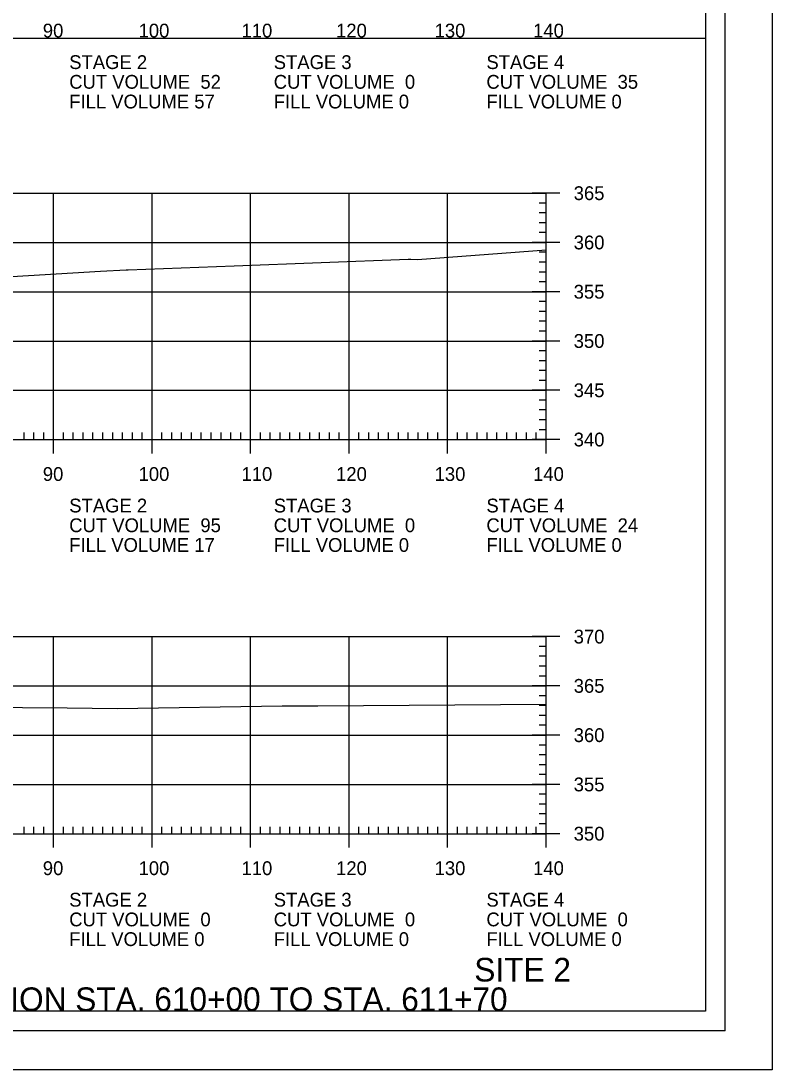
# Model space of a CAD drawing. Extents: x 1368910 to 1369601, y 380116 to 380950.
# Drawn here: x 1369524.3 to 1369600.5, y 380310.4 to 380416.9 of the extents above; entities that cross this region are included whole.
import ezdxf

# ---------------------------------------------------------------- set-up
doc = ezdxf.new("R2010")
doc.units = 0
for name, color, linetype in [('R_Axis', 7, 'Continuous'), ('R_Axis Annot', 7, 'Continuous'), ('R_Border', 7, 'Continuous'), ('R_Draft', 7, 'Continuous'), ('R_Exist Surface', 7, 'Continuous'), ('R_Grid', 7, 'Continuous'), ('R_No Plot', 7, 'Continuous')]:
    doc.layers.add(name, color=color, linetype=linetype)

msp = doc.modelspace()

# ---------------------------------------------------------------- linework, layer by layer
at = {"layer": 'R_Axis'}
for p, q in [((1369578.99, 380399.42), (1369576.19, 380399.42)), ((1369577.59, 380374.42), (1369577.59, 380399.42)), ((1369577.59, 380398.42), (1369576.89, 380398.42)), ((1369577.59, 380397.42), (1369576.89, 380397.42)), ((1369577.59, 380396.42), (1369576.89, 380396.42)), ((1369577.59, 380395.42), (1369576.89, 380395.42)), ((1369578.99, 380394.42), (1369576.19, 380394.42)), ((1369577.59, 380393.42), (1369576.89, 380393.42)), ((1369577.59, 380392.42), (1369576.89, 380392.42)), ((1369577.59, 380391.42), (1369576.89, 380391.42)), ((1369577.59, 380390.42), (1369576.89, 380390.42)), ((1369578.99, 380389.42), (1369576.19, 380389.42)), ((1369577.59, 380388.42), (1369576.89, 380388.42)), ((1369577.59, 380387.42), (1369576.89, 380387.42)), ((1369577.59, 380386.42), (1369576.89, 380386.42)), ((1369577.59, 380385.42), (1369576.89, 380385.42)), ((1369578.99, 380384.42), (1369576.19, 380384.42)), ((1369577.59, 380383.42), (1369576.89, 380383.42)), ((1369577.59, 380382.42), (1369576.89, 380382.42)), ((1369577.59, 380381.42), (1369576.89, 380381.42)), ((1369577.59, 380380.42), (1369576.89, 380380.42)), ((1369578.99, 380379.42), (1369576.19, 380379.42)), ((1369577.59, 380378.42), (1369576.89, 380378.42)), ((1369577.59, 380377.42), (1369576.89, 380377.42)), ((1369527.59, 380373.02), (1369527.59, 380375.82)), ((1369537.59, 380373.02), (1369537.59, 380375.82)), ((1369547.59, 380373.02), (1369547.59, 380375.82)), ((1369557.59, 380373.02), (1369557.59, 380375.82)), ((1369567.59, 380373.02), (1369567.59, 380375.82)), ((1369577.59, 380376.42), (1369576.89, 380376.42)), ((1369577.59, 380373.02), (1369577.59, 380375.82)), ((1369524.59, 380374.42), (1369524.59, 380375.12)), ((1369525.59, 380374.42), (1369525.59, 380375.12)), ((1369526.59, 380374.42), (1369526.59, 380375.12)), ((1369528.59, 380374.42), (1369528.59, 380375.12)), ((1369529.59, 380374.42), (1369529.59, 380375.12)), ((1369530.59, 380374.42), (1369530.59, 380375.12)), ((1369531.59, 380374.42), (1369531.59, 380375.12)), ((1369532.59, 380374.42), (1369532.59, 380375.12)), ((1369533.59, 380374.42), (1369533.59, 380375.12)), ((1369534.59, 380374.42), (1369534.59, 380375.12)), ((1369535.59, 380374.42), (1369535.59, 380375.12)), ((1369536.59, 380374.42), (1369536.59, 380375.12)), ((1369538.59, 380374.42), (1369538.59, 380375.12)), ((1369539.59, 380374.42), (1369539.59, 380375.12)), ((1369540.59, 380374.42), (1369540.59, 380375.12)), ((1369541.59, 380374.42), (1369541.59, 380375.12)), ((1369542.59, 380374.42), (1369542.59, 380375.12)), ((1369543.59, 380374.42), (1369543.59, 380375.12)), ((1369544.59, 380374.42), (1369544.59, 380375.12)), ((1369545.59, 380374.42), (1369545.59, 380375.12)), ((1369546.59, 380374.42), (1369546.59, 380375.12)), ((1369548.59, 380374.42), (1369548.59, 380375.12)), ((1369549.59, 380374.42), (1369549.59, 380375.12)), ((1369550.59, 380374.42), (1369550.59, 380375.12)), ((1369551.59, 380374.42), (1369551.59, 380375.12)), ((1369552.59, 380374.42), (1369552.59, 380375.12)), ((1369553.59, 380374.42), (1369553.59, 380375.12)), ((1369554.59, 380374.42), (1369554.59, 380375.12)), ((1369555.59, 380374.42), (1369555.59, 380375.12)), ((1369556.59, 380374.42), (1369556.59, 380375.12)), ((1369558.59, 380374.42), (1369558.59, 380375.12)), ((1369559.59, 380374.42), (1369559.59, 380375.12)), ((1369560.59, 380374.42), (1369560.59, 380375.12)), ((1369561.59, 380374.42), (1369561.59, 380375.12)), ((1369562.59, 380374.42), (1369562.59, 380375.12)), ((1369563.59, 380374.42), (1369563.59, 380375.12)), ((1369564.59, 380374.42), (1369564.59, 380375.12)), ((1369565.59, 380374.42), (1369565.59, 380375.12)), ((1369566.59, 380374.42), (1369566.59, 380375.12)), ((1369568.59, 380374.42), (1369568.59, 380375.12)), ((1369569.59, 380374.42), (1369569.59, 380375.12)), ((1369570.59, 380374.42), (1369570.59, 380375.12)), ((1369571.59, 380374.42), (1369571.59, 380375.12)), ((1369572.59, 380374.42), (1369572.59, 380375.12)), ((1369573.59, 380374.42), (1369573.59, 380375.12)), ((1369574.59, 380374.42), (1369574.59, 380375.12)), ((1369575.59, 380374.42), (1369575.59, 380375.12)), ((1369576.59, 380374.42), (1369576.59, 380375.12)), ((1369577.59, 380375.42), (1369576.89, 380375.42)), ((1369297.59, 380374.42), (1369577.59, 380374.42)), ((1369578.99, 380374.42), (1369576.19, 380374.42)), ((1369578.99, 380354.42), (1369576.19, 380354.42)), ((1369577.59, 380353.42), (1369576.89, 380353.42)), ((1369577.59, 380334.42), (1369577.59, 380354.42)), ((1369577.59, 380352.42), (1369576.89, 380352.42)), ((1369577.59, 380351.42), (1369576.89, 380351.42)), ((1369577.59, 380350.42), (1369576.89, 380350.42)), ((1369578.99, 380349.42), (1369576.19, 380349.42)), ((1369577.59, 380348.42), (1369576.89, 380348.42)), ((1369577.59, 380347.42), (1369576.89, 380347.42)), ((1369577.59, 380346.42), (1369576.89, 380346.42)), ((1369577.59, 380345.42), (1369576.89, 380345.42)), ((1369578.99, 380344.42), (1369576.19, 380344.42)), ((1369577.59, 380343.42), (1369576.89, 380343.42)), ((1369577.59, 380342.42), (1369576.89, 380342.42)), ((1369577.59, 380341.42), (1369576.89, 380341.42)), ((1369577.59, 380340.42), (1369576.89, 380340.42)), ((1369578.99, 380339.42), (1369576.19, 380339.42)), ((1369577.59, 380338.42), (1369576.89, 380338.42)), ((1369577.59, 380337.42), (1369576.89, 380337.42)), ((1369577.59, 380336.42), (1369576.89, 380336.42)), ((1369527.59, 380333.02), (1369527.59, 380335.82)), ((1369537.59, 380333.02), (1369537.59, 380335.82)), ((1369547.59, 380333.02), (1369547.59, 380335.82)), ((1369557.59, 380333.02), (1369557.59, 380335.82)), ((1369567.59, 380333.02), (1369567.59, 380335.82)), ((1369577.59, 380335.42), (1369576.89, 380335.42)), ((1369577.59, 380333.02), (1369577.59, 380335.82)), ((1369297.59, 380334.42), (1369577.59, 380334.42)), ((1369524.59, 380334.42), (1369524.59, 380335.12)), ((1369525.59, 380334.42), (1369525.59, 380335.12)), ((1369526.59, 380334.42), (1369526.59, 380335.12)), ((1369528.59, 380334.42), (1369528.59, 380335.12)), ((1369529.59, 380334.42), (1369529.59, 380335.12)), ((1369530.59, 380334.42), (1369530.59, 380335.12)), ((1369531.59, 380334.42), (1369531.59, 380335.12)), ((1369532.59, 380334.42), (1369532.59, 380335.12)), ((1369533.59, 380334.42), (1369533.59, 380335.12)), ((1369534.59, 380334.42), (1369534.59, 380335.12)), ((1369535.59, 380334.42), (1369535.59, 380335.12)), ((1369536.59, 380334.42), (1369536.59, 380335.12)), ((1369538.59, 380334.42), (1369538.59, 380335.12)), ((1369539.59, 380334.42), (1369539.59, 380335.12)), ((1369540.59, 380334.42), (1369540.59, 380335.12)), ((1369541.59, 380334.42), (1369541.59, 380335.12)), ((1369542.59, 380334.42), (1369542.59, 380335.12)), ((1369543.59, 380334.42), (1369543.59, 380335.12)), ((1369544.59, 380334.42), (1369544.59, 380335.12)), ((1369545.59, 380334.42), (1369545.59, 380335.12)), ((1369546.59, 380334.42), (1369546.59, 380335.12)), ((1369548.59, 380334.42), (1369548.59, 380335.12)), ((1369549.59, 380334.42), (1369549.59, 380335.12)), ((1369550.59, 380334.42), (1369550.59, 380335.12)), ((1369551.59, 380334.42), (1369551.59, 380335.12)), ((1369552.59, 380334.42), (1369552.59, 380335.12)), ((1369553.59, 380334.42), (1369553.59, 380335.12)), ((1369554.59, 380334.42), (1369554.59, 380335.12)), ((1369555.59, 380334.42), (1369555.59, 380335.12)), ((1369556.59, 380334.42), (1369556.59, 380335.12)), ((1369558.59, 380334.42), (1369558.59, 380335.12)), ((1369559.59, 380334.42), (1369559.59, 380335.12)), ((1369560.59, 380334.42), (1369560.59, 380335.12)), ((1369561.59, 380334.42), (1369561.59, 380335.12)), ((1369562.59, 380334.42), (1369562.59, 380335.12)), ((1369563.59, 380334.42), (1369563.59, 380335.12)), ((1369564.59, 380334.42), (1369564.59, 380335.12)), ((1369565.59, 380334.42), (1369565.59, 380335.12)), ((1369566.59, 380334.42), (1369566.59, 380335.12)), ((1369568.59, 380334.42), (1369568.59, 380335.12)), ((1369569.59, 380334.42), (1369569.59, 380335.12)), ((1369570.59, 380334.42), (1369570.59, 380335.12)), ((1369571.59, 380334.42), (1369571.59, 380335.12)), ((1369572.59, 380334.42), (1369572.59, 380335.12)), ((1369573.59, 380334.42), (1369573.59, 380335.12)), ((1369574.59, 380334.42), (1369574.59, 380335.12)), ((1369575.59, 380334.42), (1369575.59, 380335.12)), ((1369578.99, 380334.42), (1369576.19, 380334.42)), ((1369576.59, 380334.42), (1369576.59, 380335.12))]:
    msp.add_line(p, q, dxfattribs=at)
at = {"layer": 'R_Border'}
for q in [(1369595.77, 380519.88), (1369279.59, 380314.42)]:
    msp.add_line((1369595.77, 380314.42), q, dxfattribs=at)
at = {"layer": 'R_Exist Surface'}
for points in [[(1369514.91, 380390.47), (1369532.35, 380391.49), (1369534.95, 380391.64), (1369535.16, 380391.65), (1369545.92, 380392.06), (1369563.58, 380392.71), (1369563.86, 380392.74), (1369564.52, 380392.69), (1369577.59, 380393.66)], [(1369515.3, 380347.29), (1369528.98, 380347.21), (1369534.05, 380347.13), (1369550.78, 380347.38), (1369552.35, 380347.38), (1369554.43, 380347.41), (1369577.59, 380347.56)]]:
    msp.add_lwpolyline(points, dxfattribs=at)
at = {"layer": 'R_Grid'}
for p, q in [((1369297.59, 380399.42), (1369577.59, 380399.42)), ((1369527.59, 380374.42), (1369527.59, 380399.42)), ((1369537.59, 380374.42), (1369537.59, 380399.42)), ((1369547.59, 380374.42), (1369547.59, 380399.42)), ((1369557.59, 380374.42), (1369557.59, 380399.42)), ((1369567.59, 380374.42), (1369567.59, 380399.42)), ((1369577.59, 380374.42), (1369577.59, 380399.42)), ((1369297.59, 380394.42), (1369577.59, 380394.42)), ((1369297.59, 380389.42), (1369577.59, 380389.42)), ((1369297.59, 380384.42), (1369577.59, 380384.42)), ((1369297.59, 380379.42), (1369577.59, 380379.42)), ((1369297.59, 380374.42), (1369577.59, 380374.42)), ((1369297.59, 380354.42), (1369577.59, 380354.42)), ((1369527.59, 380334.42), (1369527.59, 380354.42)), ((1369537.59, 380334.42), (1369537.59, 380354.42)), ((1369547.59, 380334.42), (1369547.59, 380354.42)), ((1369557.59, 380334.42), (1369557.59, 380354.42)), ((1369567.59, 380334.42), (1369567.59, 380354.42)), ((1369577.59, 380334.42), (1369577.59, 380354.42)), ((1369297.59, 380349.42), (1369577.59, 380349.42)), ((1369297.59, 380344.42), (1369577.59, 380344.42)), ((1369297.59, 380339.42), (1369577.59, 380339.42)), ((1369297.59, 380334.42), (1369577.59, 380334.42))]:
    msp.add_line(p, q, dxfattribs=at)
at = {"layer": 'R_No Plot'}
for points in [[(1369267.18, 380523.78), (1369600.52, 380523.78), (1369600.52, 380310.44), (1369267.18, 380310.44)], [(1369281.59, 380517.88), (1369531.13, 380517.88), (1369531.13, 380508), (1369548.67, 380508), (1369572.77, 380508), (1369572.77, 380485.67), (1369593.77, 380485.67), (1369593.77, 380316.42), (1369281.59, 380316.42)], [(1369281.59, 380415.15), (1369593.77, 380415.15), (1369593.77, 380316.42), (1369281.59, 380316.42)]]:
    msp.add_lwpolyline(points, close=True, dxfattribs=at)

# ---------------------------------------------------------------- texts
at = {"layer": 'R_Axis Annot'}
for s, p in [('90', (1369526.5, 380415.22)), ('100', (1369536.22, 380415.22)), ('110', (1369546.67, 380415.22)), ('120', (1369556.27, 380415.22)), ('130', (1369566.27, 380415.22)), ('140', (1369576.27, 380415.22)), ('STAGE 2', (1369529.18, 380412.02)), ('STAGE 3', (1369549.94, 380412.02)), ('STAGE 4', (1369571.53, 380412.02)), ('CUT VOLUME  52', (1369529.18, 380410.02)), ('CUT VOLUME  0', (1369549.94, 380410.02)), ('CUT VOLUME  35', (1369571.53, 380410.02)), ('FILL VOLUME 57', (1369529.18, 380408.02)), ('FILL VOLUME 0', (1369549.94, 380408.02)), ('FILL VOLUME 0', (1369571.53, 380408.02)), ('365', (1369580.39, 380398.72)), ('360', (1369580.39, 380393.72)), ('355', (1369580.39, 380388.72)), ('350', (1369580.39, 380383.72)), ('345', (1369580.39, 380378.72)), ('340', (1369580.39, 380373.72)), ('90', (1369526.5, 380370.22)), ('100', (1369536.22, 380370.22)), ('110', (1369546.67, 380370.22)), ('120', (1369556.27, 380370.22)), ('130', (1369566.27, 380370.22)), ('140', (1369576.27, 380370.22)), ('STAGE 2', (1369529.18, 380367.02)), ('STAGE 3', (1369549.94, 380367.02)), ('STAGE 4', (1369571.53, 380367.02)), ('CUT VOLUME  95', (1369529.18, 380365.02)), ('CUT VOLUME  0', (1369549.94, 380365.02)), ('CUT VOLUME  24', (1369571.53, 380365.02)), ('FILL VOLUME 17', (1369529.18, 380363.02)), ('FILL VOLUME 0', (1369549.94, 380363.02)), ('FILL VOLUME 0', (1369571.53, 380363.02)), ('370', (1369580.39, 380353.72)), ('365', (1369580.39, 380348.72)), ('360', (1369580.39, 380343.72)), ('355', (1369580.39, 380338.72)), ('350', (1369580.39, 380333.72)), ('90', (1369526.5, 380330.22)), ('100', (1369536.22, 380330.22)), ('110', (1369546.67, 380330.22)), ('120', (1369556.27, 380330.22)), ('130', (1369566.27, 380330.22)), ('140', (1369576.27, 380330.22)), ('STAGE 2', (1369529.18, 380327.02)), ('STAGE 3', (1369549.94, 380327.02)), ('STAGE 4', (1369571.53, 380327.02)), ('CUT VOLUME  0', (1369529.18, 380325.02)), ('CUT VOLUME  0', (1369549.94, 380325.02)), ('CUT VOLUME  0', (1369571.53, 380325.02)), ('FILL VOLUME 0', (1369529.18, 380323.02)), ('FILL VOLUME 0', (1369549.94, 380323.02)), ('FILL VOLUME 0', (1369571.53, 380323.02))]:
    msp.add_text(s, height=1.4, dxfattribs=at).set_placement(p)
at = {"layer": 'R_Draft'}
for s, p in [('SITE 2', (1369570.3, 380319.42)), ('CROSS SECTION STA. 610+00 TO STA. 611+70', (1369502.33, 380316.42))]:
    msp.add_text(s, height=2.4, dxfattribs=at).set_placement(p)

doc.saveas('drawing.dxf')
